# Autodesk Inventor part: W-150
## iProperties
Author: Administrator
Revision Number: A
Created: 2001-03
Part Number: W-150
Document SubType Name: Modeling
Designer: Administrator
Description: HUB, 1.5" DIA
Control State: 0
Master: False
Checked Out: False
PropertySet Name: Design Tracking Control
Shininess: 20.0
PropertySet Name: _Private Model Information
Density: 0.0
Volumn: 0.0
Area: 0.0
PropertySet Name: Model Information
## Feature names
1. Derived Body1 [Tagging]
